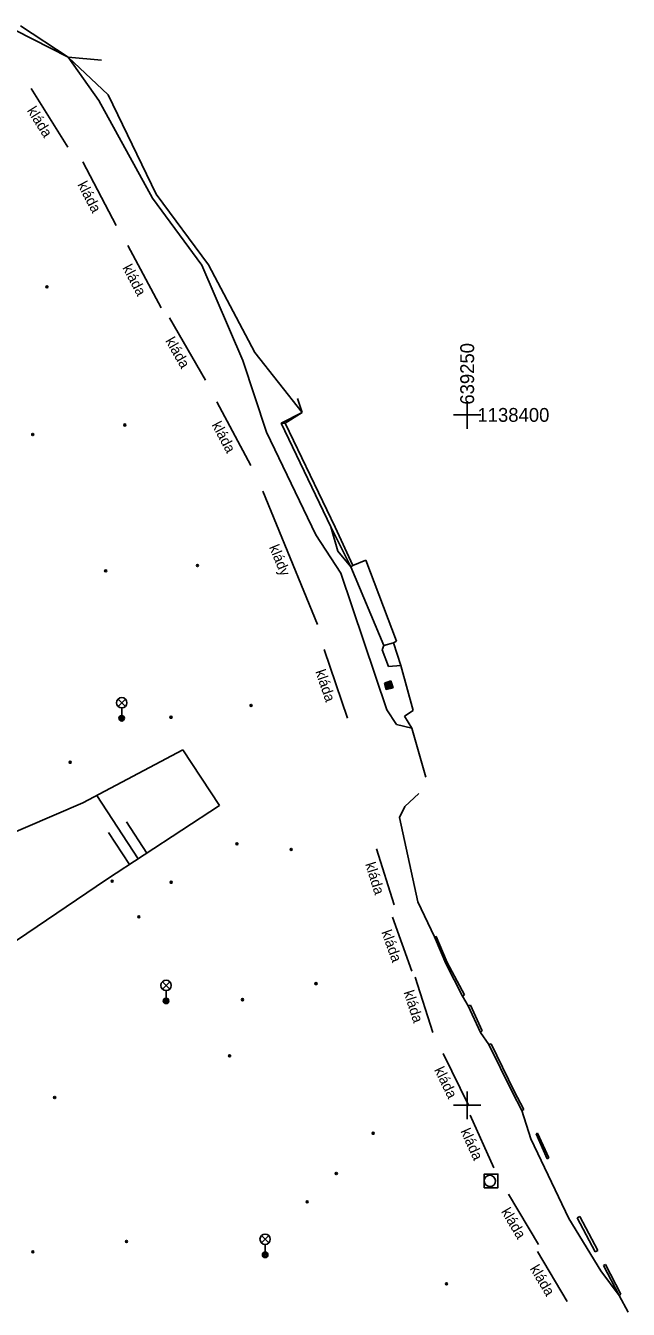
# Model space of a CAD drawing. Extents: x -639440 to -639026, y -1138850 to -1138262.
# Drawn here: x -639281.9 to -639238.3, y -1138464.8 to -1138371.8 of the extents above; entities that cross this region are included whole.
import ezdxf

# ---------------------------------------------------------------- set-up
doc = ezdxf.new("R2010")
doc.units = 0
for name, color, linetype in [('Vrstva 10', 7, 'Continuous'), ('Vrstva 11', 7, 'Continuous'), ('Vrstva 14', 7, 'Continuous'), ('Vrstva 15', 7, 'Continuous'), ('Vrstva 20', 7, 'Continuous'), ('Vrstva 25', 7, 'Continuous'), ('Vrstva 26', 7, 'Continuous'), ('Vrstva 33', 7, 'Continuous'), ('Vrstva 41', 7, 'Continuous'), ('Vrstva 58', 7, 'Continuous'), ('Vrstva 61', 7, 'Continuous'), ('Vrstva 7', 7, 'Continuous')]:
    doc.layers.add(name, color=color, linetype=linetype)

msp = doc.modelspace()

# ---------------------------------------------------------------- linework, layer by layer
at = {"layer": 'Vrstva 10'}
for p, q in [((-639282.7, -1138372.13), (-639278.87, -1138374.1)), ((-639278.87, -1138374.1), (-639276.66, -1138377.23)), ((-639276.66, -1138377.23), (-639272.76, -1138384.3)), ((-639272.76, -1138384.3), (-639269.21, -1138389.15)), ((-639269.21, -1138389.15), (-639266.24, -1138396.07)), ((-639266.24, -1138396.07), (-639264.51, -1138401.25)), ((-639264.51, -1138401.25), (-639260.95, -1138408.68)), ((-639260.95, -1138408.68), (-639259.14, -1138411.46)), ((-639259.14, -1138411.46), (-639255.81, -1138421.37)), ((-639255.81, -1138421.37), (-639255.11, -1138422.42)), ((-639255.11, -1138422.42), (-639254, -1138422.69)), ((-639254, -1138422.69), (-639252.99, -1138426.23)), ((-639253.51, -1138427.41), (-639254.5, -1138428.37)), ((-639254.5, -1138428.37), (-639254.9, -1138429.16)), ((-639254.9, -1138429.16), (-639253.57, -1138435.27)), ((-639253.57, -1138435.27), (-639252.37, -1138437.79)), ((-639252.37, -1138437.79), (-639251.55, -1138439.74)), ((-639251.55, -1138439.74), (-639250.33, -1138442.09)), ((-639250.33, -1138442.09), (-639249.93, -1138442.81)), ((-639249.93, -1138442.81), (-639249.04, -1138444.72)), ((-639249.04, -1138444.72), (-639248.44, -1138445.6)), ((-639248.44, -1138445.6), (-639246.75, -1138449.03)), ((-639246.75, -1138449.03), (-639246.05, -1138450.38)), ((-639246.05, -1138450.38), (-639245.39, -1138452.42)), ((-639245.39, -1138452.42), (-639242.65, -1138458.21)), ((-639242.65, -1138458.21), (-639240.32, -1138461.99)), ((-639240.32, -1138461.99), (-639239.01, -1138463.77)), ((-639239.01, -1138463.77), (-639238.34, -1138464.98))]:
    msp.add_line(p, q, dxfattribs=at)
at = {"layer": 'Vrstva 11'}
for p, q in [((-639263.18, -1138400.61), (-639263.45, -1138400.59)), ((-639263.45, -1138400.59), (-639259.86, -1138408.1)), ((-639263.18, -1138400.61), (-639259.56, -1138408.12)), ((-639259.86, -1138408.1), (-639258.41, -1138411)), ((-639259.56, -1138408.12), (-639258.28, -1138410.91)), ((-639258.41, -1138411), (-639258.28, -1138410.91)), ((-639258.41, -1138411), (-639256.03, -1138416.71)), ((-639258.28, -1138410.91), (-639257.34, -1138410.52)), ((-639256.03, -1138416.71), (-639256.14, -1138417.01)), ((-639255.32, -1138416.51), (-639256.03, -1138416.71)), ((-639255.11, -1138416.39), (-639255.32, -1138416.51)), ((-639255.32, -1138416.51), (-639254.79, -1138418.14)), ((-639256.14, -1138417.01), (-639255.69, -1138418.22)), ((-639255.69, -1138418.22), (-639254.79, -1138418.14)), ((-639254.79, -1138418.14), (-639253.92, -1138421.41)), ((-639255.52, -1138419.25), (-639255.99, -1138419.42)), ((-639255.99, -1138419.42), (-639255.86, -1138419.9)), ((-639255.35, -1138419.76), (-639255.52, -1138419.25)), ((-639255.86, -1138419.9), (-639255.35, -1138419.76)), ((-639253.92, -1138421.41), (-639254.53, -1138421.83)), ((-639254.53, -1138421.83), (-639254, -1138422.69)), ((-639252.37, -1138437.79), (-639252.24, -1138437.77)), ((-639252.24, -1138437.77), (-639251.44, -1138439.65)), ((-639251.44, -1138439.65), (-639250.19, -1138442.01)), ((-639250.19, -1138442.01), (-639250.33, -1138442.09)), ((-639249.93, -1138442.81), (-639249.77, -1138442.75)), ((-639249.77, -1138442.75), (-639248.91, -1138444.62)), ((-639248.91, -1138444.62), (-639249.04, -1138444.72)), ((-639248.44, -1138445.6), (-639248.27, -1138445.55)), ((-639248.27, -1138445.55), (-639246.61, -1138448.99)), ((-639246.61, -1138448.99), (-639245.89, -1138450.31)), ((-639245.89, -1138450.31), (-639246.05, -1138450.38)), ((-639245.01, -1138452.06), (-639244.9, -1138452.02)), ((-639244.2, -1138453.87), (-639245.01, -1138452.06)), ((-639244.9, -1138452.02), (-639244.09, -1138453.81)), ((-639244.09, -1138453.81), (-639244.2, -1138453.87)), ((-639242.04, -1138458.15), (-639241.84, -1138458.05)), ((-639240.73, -1138460.61), (-639242.04, -1138458.15)), ((-639241.84, -1138458.05), (-639240.55, -1138460.51)), ((-639240.55, -1138460.51), (-639240.73, -1138460.61)), ((-639240.14, -1138461.6), (-639240, -1138461.53)), ((-639239.01, -1138463.77), (-639240.14, -1138461.6)), ((-639240, -1138461.53), (-639238.89, -1138463.67)), ((-639238.89, -1138463.67), (-639239.01, -1138463.77))]:
    msp.add_line(p, q, dxfattribs=at)
msp.add_ellipse((-639248.361, -1138455.479), major_axis=(0.308, -0.274), ratio=0.994642, dxfattribs=at)
at = {"layer": 'Vrstva 14'}
for p, q in [((-639282.33, -1138371.81), (-639278.87, -1138374.1)), ((-639278.87, -1138374.1), (-639275.98, -1138376.82)), ((-639276.47, -1138374.3), (-639278.87, -1138374.1)), ((-639275.98, -1138376.82), (-639272.5, -1138384.02)), ((-639272.5, -1138384.02), (-639268.72, -1138389.12)), ((-639268.72, -1138389.12), (-639265.36, -1138395.49)), ((-639265.36, -1138395.49), (-639261.94, -1138399.83)), ((-639261.94, -1138399.83), (-639262.27, -1138398.82)), ((-639261.94, -1138399.83), (-639263.45, -1138400.59)), ((-639261.94, -1138399.83), (-639263.18, -1138400.61)), ((-639259.86, -1138408.1), (-639259.37, -1138409.87)), ((-639259.37, -1138409.87), (-639258.41, -1138411)), ((-639270.58, -1138424.25), (-639277.82, -1138428.1)), ((-639267.92, -1138428.3), (-639270.58, -1138424.25)), ((-639277.82, -1138428.1), (-639284.21, -1138430.85)), ((-639267.92, -1138428.3), (-639276.1, -1138433.64)), ((-639276.1, -1138433.64), (-639284.23, -1138439.15))]:
    msp.add_line(p, q, dxfattribs=at)
at = {"layer": 'Vrstva 15'}
for p, q in [((-639273.81, -1138432.145), (-639276.804, -1138427.559)), ((-639273.182, -1138431.735), (-639274.66, -1138429.471)), ((-639274.438, -1138432.555), (-639275.953, -1138430.234))]:
    msp.add_line(p, q, dxfattribs=at)
at = {"layer": 'Vrstva 20'}
for centre, radius in [((-639280.41, -1138390.73), 0.075), ((-639280.41, -1138390.73), 0.0204), ((-639274.78, -1138400.73), 0.075), ((-639274.78, -1138400.73), 0.0204), ((-639281.44, -1138401.42), 0.075), ((-639281.44, -1138401.42), 0.0204), ((-639269.52, -1138410.91), 0.075), ((-639269.52, -1138410.91), 0.0204), ((-639276.16, -1138411.3), 0.075), ((-639276.16, -1138411.3), 0.0204), ((-639265.64, -1138421.04), 0.075), ((-639265.64, -1138421.04), 0.0204), ((-639271.43, -1138421.9), 0.075), ((-639271.43, -1138421.9), 0.0204), ((-639278.73, -1138425.16), 0.075), ((-639278.73, -1138425.16), 0.0204), ((-639266.66, -1138431.06), 0.075), ((-639266.66, -1138431.06), 0.0204), ((-639262.73, -1138431.47), 0.075), ((-639262.73, -1138431.47), 0.0204), ((-639275.69, -1138433.77), 0.075), ((-639275.69, -1138433.77), 0.0204), ((-639271.42, -1138433.85), 0.075), ((-639271.42, -1138433.85), 0.0204), ((-639273.76, -1138436.36), 0.075), ((-639273.76, -1138436.36), 0.0204), ((-639260.94, -1138441.19), 0.075), ((-639260.94, -1138441.19), 0.0204), ((-639266.26, -1138442.35), 0.075), ((-639266.26, -1138442.35), 0.0204), ((-639267.19, -1138446.42), 0.075), ((-639267.19, -1138446.42), 0.0204), ((-639279.85, -1138449.44), 0.075), ((-639279.85, -1138449.44), 0.0204), ((-639256.8, -1138452.03), 0.075), ((-639256.8, -1138452.03), 0.0204), ((-639259.47, -1138454.94), 0.075), ((-639259.47, -1138454.94), 0.0204), ((-639261.58, -1138457), 0.075), ((-639261.58, -1138457), 0.0204), ((-639274.65, -1138459.86), 0.075), ((-639274.65, -1138459.86), 0.0204), ((-639281.43, -1138460.61), 0.075), ((-639281.43, -1138460.61), 0.0204), ((-639251.5, -1138462.94), 0.075), ((-639251.5, -1138462.94), 0.0204)]:
    msp.add_circle(centre, radius, dxfattribs=at)
at = {"layer": 'Vrstva 25'}
for radius in [0.25, 0.2, 0.15, 0.1, 0.05]:
    msp.add_circle((-639255.69, -1138419.58), radius, dxfattribs=at)
at = {"layer": 'Vrstva 26'}
msp.add_lwpolyline([(-639248.77, -1138455.98), (-639247.77, -1138455.98), (-639247.77, -1138454.98), (-639248.77, -1138454.98)], close=True, dxfattribs=at)
at = {"layer": 'Vrstva 33'}
for p, q in [((-639275.265, -1138421.11), (-639274.735, -1138420.58)), ((-639275.265, -1138420.58), (-639274.735, -1138421.11)), ((-639275, -1138421.22), (-639275, -1138421.97)), ((-639272.055, -1138441.58), (-639271.525, -1138441.05)), ((-639272.055, -1138441.05), (-639271.525, -1138441.58)), ((-639271.79, -1138441.69), (-639271.79, -1138442.44)), ((-639264.885, -1138459.97), (-639264.355, -1138459.44)), ((-639264.885, -1138459.44), (-639264.355, -1138459.97)), ((-639264.62, -1138460.08), (-639264.62, -1138460.83))]:
    msp.add_line(p, q, dxfattribs=at)
for centre, radius in [((-639275, -1138420.845), 0.375), ((-639275, -1138421.97), 0.2), ((-639275, -1138421.97), 0.145), ((-639275, -1138421.97), 0.0876), ((-639271.79, -1138441.315), 0.375), ((-639271.79, -1138442.44), 0.2), ((-639271.79, -1138442.44), 0.145), ((-639271.79, -1138442.44), 0.0876), ((-639264.62, -1138459.705), 0.375), ((-639264.62, -1138460.83), 0.2), ((-639264.62, -1138460.83), 0.145), ((-639264.62, -1138460.83), 0.0876)]:
    msp.add_circle(centre, radius, dxfattribs=at)
at = {"layer": 'Vrstva 58'}
for p, q in [((-639281.55, -1138376.36), (-639278.89, -1138380.6)), ((-639277.82, -1138381.66), (-639275.4, -1138386.29)), ((-639274.56, -1138387.72), (-639272.15, -1138392.25)), ((-639271.53, -1138392.96), (-639268.93, -1138397.48)), ((-639268.12, -1138399.06), (-639265.66, -1138403.66)), ((-639264.79, -1138405.53), (-639262.81, -1138410.36)), ((-639262.81, -1138410.36), (-639260.83, -1138415.19)), ((-639260.35, -1138417), (-639258.66, -1138421.96)), ((-639255.29, -1138435.48), (-639256.55, -1138431.44)), ((-639254.01, -1138440.28), (-639255.41, -1138436.37)), ((-639252.49, -1138444.74), (-639253.77, -1138440.73)), ((-639249.89, -1138450.03), (-639251.73, -1138446.24)), ((-639248.06, -1138454.53), (-639249.79, -1138450.71)), ((-639244.84, -1138460.09), (-639247, -1138456.44)), ((-639242.76, -1138464.21), (-639244.92, -1138460.58))]:
    msp.add_line(p, q, dxfattribs=at)
at = {"layer": 'Vrstva 61'}
for p, q in [((-639250, -1138399), (-639250, -1138401)), ((-639251, -1138400), (-639249, -1138400)), ((-639250, -1138449), (-639250, -1138451)), ((-639251, -1138450), (-639249, -1138450))]:
    msp.add_line(p, q, dxfattribs=at)
at = {"layer": 'Vrstva 7'}
msp.add_line((-639257.34, -1138410.52), (-639255.11, -1138416.39), dxfattribs=at)

# ---------------------------------------------------------------- texts
at = {"layer": 'Vrstva 41'}
for s, rotation, p in [('kláda', 302.10245, (-639281.879, -1138377.953)), ('kláda', 297.59509, (-639278.222, -1138383.319)), ('kláda', 298.01337, (-639274.972, -1138389.341)), ('kláda', 299.90843, (-639271.868, -1138394.629)), ('kláda', 298.1371, (-639268.509, -1138400.719)), ('klády', 292.29058, (-639264.348, -1138409.574)), ('kláda', 288.8153, (-639260.998, -1138418.585)), ('kláda', 287.32172, (-639257.389, -1138432.527)), ('kláda', 289.70022, (-639256.217, -1138437.454)), ('kláda', 287.70319, (-639254.606, -1138441.812)), ('kláda', 295.89602, (-639252.402, -1138447.431)), ('kláda', 294.3648, (-639250.498, -1138451.874)), ('kláda', 300.61623, (-639247.565, -1138457.695)), ('kláda', 300.75439, (-639245.486, -1138461.829))]:
    msp.add_text(s, height=0.75, rotation=rotation, dxfattribs=at).set_placement(p)
at = {"layer": 'Vrstva 61'}
msp.add_text('  639250', height=1, rotation=90, dxfattribs=at).set_placement((-639249.5, -1138400))
msp.add_text('  1138400', height=1, dxfattribs=at).set_placement((-639250, -1138400.5))

doc.saveas('drawing.dxf')
